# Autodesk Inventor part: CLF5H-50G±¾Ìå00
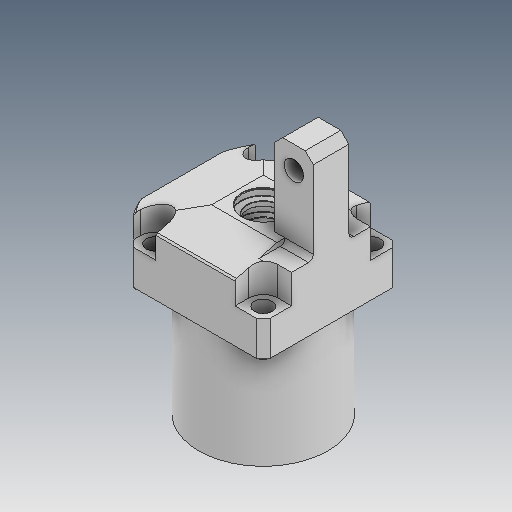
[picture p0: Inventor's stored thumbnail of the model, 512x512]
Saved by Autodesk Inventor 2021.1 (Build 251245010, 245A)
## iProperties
Created: 2014-12
Part Number: CLF5H-50G±¾Ìå00
Material: Ogólny
Document SubType Name: Modeling
Designer: user
Density: 1 g/cm^3
Appearance: Domyślna
Author: user
Revision Number: ÈÎºÎ
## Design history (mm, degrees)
feature "NONE"
node "Bryła1"
